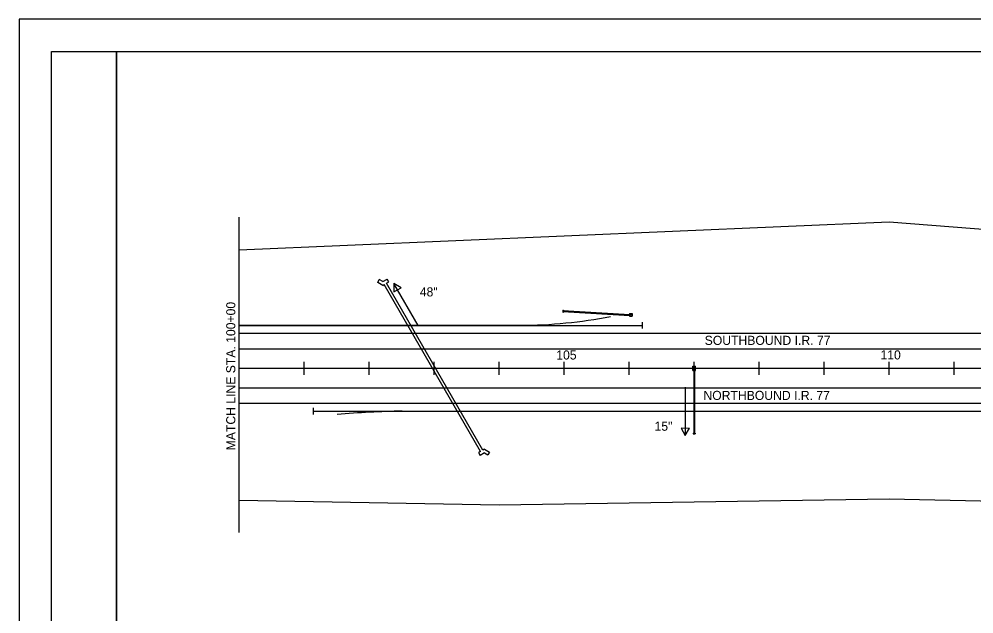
# Model space of a CAD drawing. Extents: x 0 to 3400, y 0 to 2200.
# Drawn here: x 0 to 1469, y 1285 to 2200 of the extents above; entities that cross this region are included whole.
import ezdxf

# ---------------------------------------------------------------- set-up
doc = ezdxf.new("R2010")
doc.units = 0
for name, color, linetype in [('Default', 7, 'Continuous'), ('DR_X_Culvert', 7, 'Continuous'), ('DR_X_Text', 7, 'Continuous'), ('GE_P_CL_100', 7, 'Continuous'), ('PV_P_EOP', 7, 'Continuous'), ('RD_P_GR_Lt_Replaced', 7, 'Continuous'), ('RD_X_GR_Lt', 7, 'Continuous'), ('RD_X_GR_Rt', 7, 'Continuous'), ('RW_X_Esmt_LA', 7, 'Continuous'), ('SC_Scratch10', 7, 'Continuous'), ('SH_Border', 7, 'Continuous'), ('SH_Cut_Line', 7, 'Continuous'), ('SH_Data', 7, 'Continuous')]:
    doc.layers.add(name, color=color, linetype=linetype)

msp = doc.modelspace()

# ---------------------------------------------------------------- linework, layer by layer
at = {"layer": 'Default'}
for p, q in [((338.4, 1729), (771.3, 1729)), ((338.4, 1729), (771.3, 1729)), ((338.4, 1662.8), (338.4, 1665.8)), ((338.4, 1662.8), (1838.4, 1662.8)), ((438.4, 1652.8), (438.4, 1672.8)), ((464.9, 1662.8), (464.9, 1662.8)), ((538.4, 1652.8), (538.4, 1672.8)), ((638.4, 1652.8), (638.4, 1672.8)), ((638.4, 1662.8), (638.4, 1662.8)), ((738.4, 1652.8), (738.4, 1672.8)), ((836.4, 1662.8), (836.4, 1662.8)), ((838.4, 1652.8), (838.4, 1672.8)), ((932.9, 1662.8), (932.9, 1662.8)), ((938.4, 1652.8), (938.4, 1672.8)), ((940.9, 1662.8), (940.9, 1662.8)), ((1038.4, 1652.8), (1038.4, 1672.8)), ((1038.4, 1662.8), (1038.4, 1662.8)), ((1138.4, 1652.8), (1138.4, 1672.8)), ((1238.4, 1652.8), (1238.4, 1672.8)), ((1338.4, 1652.8), (1338.4, 1672.8)), ((1438.4, 1652.8), (1438.4, 1672.8)), ((589.4, 1596.7), (1837.9, 1596.7)), ((589.4, 1596.7), (1837.9, 1596.7))]:
    msp.add_line(p, q, dxfattribs=at)
for points in [[(338.4, 1662.8), (343.4, 1662.8)], [(348.4, 1662.8), (428.4, 1662.8)], [(433.4, 1662.8), (443.4, 1662.8)], [(448.4, 1662.8), (528.4, 1662.8)], [(533.4, 1662.8), (543.4, 1662.8)], [(548.4, 1662.8), (628.4, 1662.8)], [(633.4, 1662.8), (643.4, 1662.8)], [(648.4, 1662.8), (728.4, 1662.8)], [(733.4, 1662.8), (743.4, 1662.8)], [(748.4, 1662.8), (828.4, 1662.8)], [(833.4, 1662.8), (843.4, 1662.8)], [(848.4, 1662.8), (928.4, 1662.8)], [(933.4, 1662.8), (943.4, 1662.8)], [(948.4, 1662.8), (1028.4, 1662.8)], [(1033.4, 1662.8), (1043.4, 1662.8)], [(1048.4, 1662.8), (1128.4, 1662.8)], [(1133.4, 1662.8), (1143.4, 1662.8)], [(1148.4, 1662.8), (1228.4, 1662.8)], [(1233.4, 1662.8), (1243.4, 1662.8)], [(1248.4, 1662.8), (1328.4, 1662.8)], [(1333.4, 1662.8), (1343.4, 1662.8)], [(1348.4, 1662.8), (1428.4, 1662.8)], [(1433.4, 1662.8), (1443.4, 1662.8)], [(1448.4, 1662.8), (1528.4, 1662.8)]]:
    msp.add_lwpolyline(points, dxfattribs=at)
for centre, major_axis, ratio, start_param, end_param in [((771.2, 2436.9), (-708.4, -40.6), 0.997702, 1.513763, 1.710319), ((771.2, 2436.9), (-708.4, -40.6), 0.997702, 1.513763, 1.710319), ((604.2, 339.7), (-1282, -47.7), 0.979896, 4.687514, 4.765678), ((604.2, 339.7), (-1282, -47.7), 0.979896, 4.687514, 4.765678)]:
    msp.add_ellipse(centre, major_axis=major_axis, ratio=ratio, start_param=start_param, end_param=end_param, dxfattribs=at)
at = {"layer": 'DR_X_Culvert'}
for p, q in [((551.6, 1794.7), (554.1, 1799.1)), ((559.3, 1790.3), (551.6, 1794.7)), ((559.3, 1796.1), (554.1, 1799.1)), ((559.3, 1796.1), (566.1, 1800)), ((565.2, 1793.7), (568.6, 1795.7)), ((713.4, 1536.9), (565.2, 1793.7)), ((568.6, 1795.7), (566.1, 1800)), ((559.3, 1790.3), (561.7, 1791.7)), ((710, 1534.9), (561.7, 1791.7)), ((836.5, 1752.3), (836.4, 1749.3)), ((836.4, 1750), (939.7, 1744.1)), ((836.4, 1749.3), (837.4, 1749.2)), ((836.5, 1752.3), (837.5, 1752.2)), ((836.5, 1751.5), (939.7, 1745.6)), ((837.5, 1752.2), (837.4, 1749.2)), ((939, 1746.8), (943, 1746.8)), ((939, 1746.8), (939, 1742.8)), ((939, 1742.8), (943, 1742.8)), ((939.7, 1746.1), (939.7, 1743.4)), ((939.7, 1746.1), (942.3, 1746.1)), ((939.7, 1743.4), (942.3, 1743.4)), ((942.3, 1746.1), (942.3, 1743.4)), ((943, 1746.8), (943, 1742.8)), ((1036.4, 1659.5), (1036.4, 1666.1)), ((1036.4, 1666.1), (1040.4, 1666.1)), ((1037.1, 1665.5), (1039.8, 1665.5)), ((1037.1, 1660.1), (1037.1, 1665.5)), ((1037.1, 1660.1), (1039.8, 1660.1)), ((1037.8, 1660.1), (1037.8, 1562.1)), ((1039.1, 1660.1), (1039.1, 1562.1)), ((1039.8, 1660.1), (1039.8, 1665.5)), ((1040.4, 1659.5), (1040.4, 1666.1)), ((1036.4, 1659.5), (1040.4, 1659.5)), ((1036.8, 1563.1), (1040.1, 1563.1)), ((1036.8, 1563.1), (1036.8, 1562.1)), ((1036.8, 1562.1), (1040.1, 1562.1)), ((1040.1, 1563.1), (1040.1, 1562.1)), ((710, 1534.9), (706.5, 1532.9)), ((706.5, 1532.9), (709, 1528.6)), ((715.8, 1532.5), (709, 1528.6)), ((715.8, 1538.3), (713.4, 1536.9)), ((715.8, 1538.3), (723.5, 1533.9)), ((715.8, 1532.5), (721, 1529.5)), ((723.5, 1533.9), (721, 1529.5))]:
    msp.add_line(p, q, dxfattribs=at)
at = {"layer": 'DR_X_Text'}
for p, q in [((613.7, 1728.8), (576.6, 1793.1)), ((587.6, 1786.7), (576.6, 1793.1)), ((576.6, 1793.1), (576.6, 1780.4)), ((576.6, 1780.5), (587.6, 1786.7)), ((1024.8, 1633.7), (1024.8, 1559.5)), ((1018.5, 1570.5), (1024.8, 1559.5)), ((1031.1, 1570.3), (1018.5, 1570.5)), ((1024.8, 1559.5), (1031.2, 1570.5))]:
    msp.add_line(p, q, dxfattribs=at)
at = {"layer": 'PV_P_EOP'}
for p, q in [((338.4, 1716.8), (3038.3, 1716.8)), ((338.4, 1692.8), (3038.3, 1692.8)), ((338.4, 1632.8), (3038.3, 1632.8)), ((338.4, 1608.8), (3038.3, 1608.8))]:
    msp.add_line(p, q, dxfattribs=at)
at = {"layer": 'RD_P_GR_Lt_Replaced'}
for p, q in [((958.5, 1733.8), (958.5, 1723.8)), ((452.4, 1601.8), (452.4, 1591.8))]:
    msp.add_line(p, q, dxfattribs=at)
at = {"layer": 'RD_X_GR_Lt'}
msp.add_line((338.4, 1728.8), (958.5, 1728.8), dxfattribs=at)
at = {"layer": 'RD_X_GR_Rt'}
msp.add_line((452.4, 1596.8), (1877.4, 1596.8), dxfattribs=at)
at = {"layer": 'RW_X_Esmt_LA'}
for p, q in [((338.4, 1845.2), (1338.5, 1887.8)), ((1338.5, 1887.8), (1838.4, 1849.9)), ((338.4, 1459.9), (738.5, 1452.8)), ((738.5, 1452.8), (1338.5, 1462.1)), ((1338.5, 1462.1), (1838.5, 1450.7))]:
    msp.add_line(p, q, dxfattribs=at)
at = {"layer": 'SC_Scratch10'}
for p, q in [((958.5, 1728.8), (958.5, 1728.8)), ((438.4, 1662.8), (438.4, 1662.8)), ((538.4, 1662.8), (538.4, 1662.8)), ((638.4, 1662.8), (638.4, 1662.8)), ((738.4, 1662.8), (738.4, 1662.8)), ((838.4, 1662.8), (838.4, 1662.8)), ((938.4, 1662.8), (938.4, 1662.8)), ((1038.4, 1662.8), (1038.4, 1662.8)), ((1138.4, 1662.8), (1138.4, 1662.8)), ((1238.4, 1662.8), (1238.4, 1662.8)), ((1338.4, 1662.8), (1338.4, 1662.8)), ((1438.4, 1662.8), (1438.4, 1662.8))]:
    msp.add_line(p, q, dxfattribs=at)
at = {"layer": 'SH_Border'}
for points in [[(50, 2150), (150, 2150), (150, 50), (50, 50)], [(150, 2150), (3350, 2150), (3350, 50), (150, 50)]]:
    msp.add_lwpolyline(points, close=True, dxfattribs=at)
at = {"layer": 'SH_Cut_Line'}
msp.add_line((338.4, 1662.8), (338.4, 1662.8), dxfattribs=at)
msp.add_lwpolyline([(0, 0), (3400, 0), (3400, 2200), (0, 2200)], close=True, dxfattribs=at)
at = {"layer": 'SH_Data'}
msp.add_line((338.4, 1409.9), (338.4, 1895.2), dxfattribs=at)

# ---------------------------------------------------------------- texts
at = {"layer": 'DR_X_Text'}
for s, p in [('48"', (616.4, 1773.3)), ('15"', (977.5, 1566.6))]:
    msp.add_text(s, height=14, dxfattribs=at).set_placement(p)
at = {"layer": 'GE_P_CL_100'}
for s, rotation, p in [('SOUTHBOUND I.R. 77', 0.0003, (1054.6, 1698.7)), ('105', 359.9986, (826.3, 1676.2)), ('110', 359.9986, (1325, 1676.3)), ('NORTHBOUND I.R. 77', 0.0003, (1052.7, 1614))]:
    msp.add_text(s, height=14, rotation=rotation, dxfattribs=at).set_placement(p)
at = {"layer": 'SH_Data'}
msp.add_text('MATCH LINE STA. 100+00', height=14, rotation=89.9999, dxfattribs=at).set_placement((332.6, 1536.5))

doc.saveas('drawing.dxf')
